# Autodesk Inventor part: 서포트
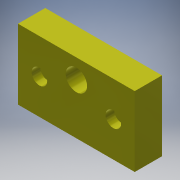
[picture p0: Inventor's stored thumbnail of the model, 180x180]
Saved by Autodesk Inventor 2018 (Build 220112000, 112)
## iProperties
Created: 2020-03
Part Number: 서포트
Material: 알루미늄 6061
Document SubType Name: Modeling
Designer: mduedu
Density: 2.71 g/cm^3
Mass: 73.7304 g
Surface Area: 81.0378 cm^2
Volume: 27.2068 cm^3
Appearance: 노란색
Author: mduedu
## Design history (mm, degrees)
sketch "스케치1"
  geometry: L1 (-30, 0)-(30, 0); L2 (30, 0)-(30, 36); L3 (30, 36)-(-30, 36); L4 (-30, 36)-(-30, 0); 2 further points
  constraints: 8 end point, 2 parallel, 1 coincident, 1 horizontal, 1 midpoint, 1 perpendicular
  dimensions: "d0" = 60 distance of L1.start L1.end; "d2" = 36 distance of L1.end L2.end
extrude "돌출1" new body sketch "스케치1" distance "d3" = 14; taper "d4" = 0 deg
sketch "스케치2"
  geometry: 3 further points
  constraints: 1 horizontal alignment
  dimensions: "d5" = 7 vertical distance of point (52, 7) point (30, 0); "d6" = 22 horizontal distance of point (8, 7) point (30, 0); "d7" = 44 distance of point (52, 7) point (8, 7)
hole "구멍1" sketch "스케치2" at (8, 7), (52, 7) diameter "d8" = 3.242; stored, may be unused: countersink angle "d12" = 90 deg, drill point angle "d14" = 118 deg; dims "d9" = 6, "d10" = 4, "d11" = 2, "d13" = 8
sketch "스케치3"
  geometry: L1 (30, 0)-(-30, 0) reference; 3 further points
  constraints: 1 midpoint, 1 vertical alignment
  dimensions: "d15" = 26 distance of point (0, 0) point (0, 26)
hole "구멍2" sketch "스케치3" at (0, 26) diameter "d16" = 11; stored, may be unused: countersink angle "d20" = 90 deg, drill point angle "d22" = 118 deg; dims "d17" = 8, "d18" = 15, "d19" = 3, "d21" = 10
sketch "스케치4"
  geometry: 3 further points
  constraints: 1 horizontal alignment
  dimensions: "d23" = 18 vertical distance of point (19, 18) point (0, 0); "d24" = 19 horizontal distance of point (-19, 18) point (0, 0); "d25" = 38 distance of point (19, 18) point (-19, 18)
hole "구멍3" sketch "스케치4" at (-19, 18), (19, 18) diameter "d26" = 4.5; stored, may be unused: countersink angle "d30" = 90 deg, drill point angle "d32" = 118 deg; dims "d27" = 8, "d28" = 8, "d29" = 4.4, "d31" = 10
sketch "스케치5"
  geometry: C1 r 2.25 at (-19, 18) reference; 1 further point
hole "구멍4" sketch "스케치5" at (-19, 18) diameter "d33" = 9; stored, may be unused: countersink angle "d37" = 90 deg, drill point angle "d39" = 0 deg; dims "d34" = 8, "d35" = 8, "d36" = 4.4, "d38" = 6
sketch "스케치6"
  geometry: C1 r 2.25 at (19, 18) reference; 1 further point
hole "구멍5" sketch "스케치6" at (19, 18) diameter "d40" = 9; stored, may be unused: countersink angle "d44" = 90 deg, drill point angle "d46" = 0 deg; dims "d41" = 8, "d42" = 8, "d43" = 4.4, "d45" = 6
node "솔리드1"
